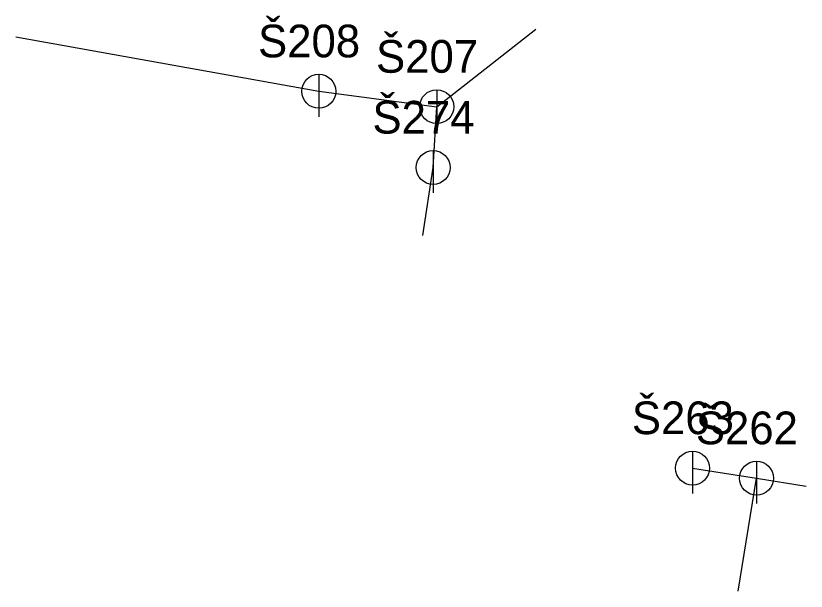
# Model space of a CAD drawing. Extents: x -482979.6 to -482933, y -1126063.1 to -1126029.2.
import ezdxf

# ---------------------------------------------------------------- set-up
doc = ezdxf.new("R2010")
doc.units = 0
for name, color, linetype in [('_pripojka_kanal_jednotna_priblizne_', 7, 'Continuous'), ('_stoka_jednotna_smvak_prevzato_z_dokumentace_', 7, 'Continuous'), ('Default', 7, 'Continuous'), ('MoLevel 119', 7, 'Continuous'), ('MoLevel 120', 7, 'Continuous')]:
    doc.layers.add(name, color=color, linetype=linetype)

# ---------------------------------------------------------------- blocks, each defined once
blk = doc.blocks.new('_sachta_kanal_prevzato_z_dokumentace_')
at = {"layer": 'Default'}
blk.add_line((0, 0.00005), (0, -0.000075), dxfattribs=at)
blk.add_circle((0, 0), 0.00005, dxfattribs=at)

msp = doc.modelspace()

# ---------------------------------------------------------------- linework, layer by layer
at = {"layer": '_pripojka_kanal_jednotna_priblizne_'}
for p, q in [((-482955.638, -1126042.1), (-482955.029, -1126038.104)), ((-482937.058, -1126063.063), (-482935.972, -1126056.406))]:
    msp.add_line(p, q, dxfattribs=at)
at = {"layer": '_stoka_jednotna_smvak_prevzato_z_dokumentace_'}
for p, q in [((-482954.82, -1126034.52), (-482948.976, -1126029.945)), ((-482979.626, -1126030.4), (-482961.771, -1126033.613)), ((-482961.771, -1126033.613), (-482954.82, -1126034.52)), ((-482955.029, -1126038.104), (-482954.82, -1126034.52)), ((-482939.742, -1126055.812), (-482935.972, -1126056.406)), ((-482935.972, -1126056.406), (-482933.044, -1126056.883))]:
    msp.add_line(p, q, dxfattribs=at)

# ---------------------------------------------------------------- block references
at = {"layer": 'MoLevel 119', "xscale": 20000, "yscale": 20000}
for p in [(-482961.771, -1126033.613), (-482954.82, -1126034.52), (-482955.029, -1126038.104), (-482939.742, -1126055.812), (-482935.972, -1126056.406)]:
    msp.add_blockref('_sachta_kanal_prevzato_z_dokumentace_', p, dxfattribs=at)

# ---------------------------------------------------------------- texts
at = {"layer": 'MoLevel 120'}
for s, p in [('Š208', (-482965.348, -1126031.613)), ('Š207', (-482958.397, -1126032.52)), ('Š274', (-482958.606, -1126036.104)), ('Š263', (-482943.319, -1126053.812)), ('Š262', (-482939.549, -1126054.406))]:
    msp.add_text(s, height=1.9259, dxfattribs=at).set_placement(p)

doc.saveas('drawing.dxf')
